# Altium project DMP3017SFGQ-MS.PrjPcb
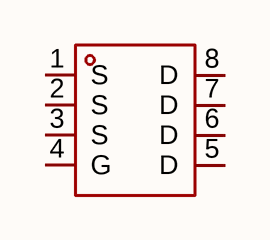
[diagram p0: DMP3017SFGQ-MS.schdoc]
1 sheet, 1 parts. Net scope: global (net labels, ports and power ports of the same name join across sheets).

## Sheet DMP3017SFGQ-MS.schdoc
size 127 x 101 mm

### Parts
Q?  dmp3017sfgq-ms  [POWERPAK-1212-8_L3.0-W3.0-P0.65-LS3.3-BL]  (value not drawn)

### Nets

Not connected (* = marked no-connect by the designer): Q? 1(S) 2(S) 3(S) 4(G) 5(D) 6(D) 7(D) 8(D)

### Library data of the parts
Q? = dmp3017sfgq-ms: 数量:1个P沟道;漏源电压(Vdss):30V;连续漏极电流(Id):55A;导通电阻(RDS(on)):8.5mΩ@10V;耗散功率(Pd):21.5W;阈值电压(Vgs(th)):1.5V;; Manufacturer: MSKSEMI(美森科); AddInBom: yes; ModelId: 74fc8db97a8d4d328d7f3b4acba39a5e; ModelTransform: 129.921,129.921,0,0,0,0,0,0,0; Number: 1个P沟道; Drain to Source Voltage: 30V; Current - Continuous Drain(Id): 55A; Pd - Power Dissipation: 21.5W; Gate Threshold Voltage (Vgs(th)): 1.5V; Gate Charge(Qg): 30nC; Input Capacitance(Ciss): 2.8nF; Reverse Transfer Capacitance (Crss@Vds): 319pF; Type: P沟道; Output Capacitance(Coss): 346pF; Vgs: ±20V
